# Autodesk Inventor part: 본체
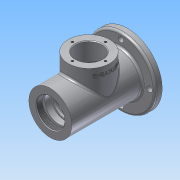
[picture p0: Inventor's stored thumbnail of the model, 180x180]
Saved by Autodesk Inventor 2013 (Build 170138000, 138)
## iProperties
Created: 2016-08
Part Number: 본체
Material: 알루미늄 6061
Document SubType Name: Modeling
Designer: Administrator
Density: 2.71 g/cm^3
Mass: 730.594 g
Surface Area: 615.602 cm^2
Volume: 269.592 cm^3
Author: Administrator
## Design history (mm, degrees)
sketch "스케치1"
  geometry: L1 (-57.5, 0)-(57.5, 0); L2 (-57.5, 0)-(-57.5, 31); L3 (-57.5, 31)-(44.5, 31); L4 (44.5, 31)-(44.5, 50); L5 (44.5, 50)-(54.5, 50); L6 (54.5, 50)-(54.5, 31); L7 (54.5, 31)-(57.5, 31); L8 (57.5, 31)-(57.5, 0); 2 further points
  constraints: 16 end point, 6 perpendicular, 1 coincident, 1 collinear, 1 horizontal, 1 midpoint, 1 parallel
  dimensions: "d0" = 100 diameter of L5 L1; "d2" = 115 distance of L1.start L1.end; "d4" = 3 horizontal distance of L7.end L5.end; "d6" = 13 distance between parallel lines of L8 L4; "d7" = 62 diameter of L3 L1
revolve "회전1" sketch "스케치1" stored, may be unused: angle "d8" = 90 deg
node "작업 평면1"
sketch "스케치2"
  geometry: L1 (57.5, 31)-(57.5, -31) reference; C1 r 30 at (1.5, 0); 1 further point
  constraints: 1 centre point, 1 horizontal alignment
  dimensions: "d10" = 60 diameter of C1; "d12" = 56 distance from line of L1 C1.centre
extrude "돌출1" join sketch "스케치2" stored distance "d13" = 10; taper "d14" = 0 deg
sketch "스케치3"
  geometry: L1 (57.5, 0)-(-48.5, 0); L2 (57.5, -31)-(57.5, 31) reference; L3 (57.5, 0)-(57.5, 21); L4 (57.5, 21)-(43.5, 16); L5 (43.5, 16)-(43.5, 12.5); L6 (43.5, 12.5)-(36.2, 12.5); L7 (36.2, 12.5)-(36.2, 10); L8 (36.2, 10)-(33.5, 10); L9 (33.5, 10)-(33.5, 16.5); L10 (33.5, 16.5)-(28.5, 16.5); L11 (28.5, 16.5)-(28.5, 17.5); L12 (28.5, 17.5)-(17.5, 17.5); L13 (17.5, 17.5)-(17.5, 26); L14 (17.5, 26)-(-20.5, 26); L15 (-20.5, 26)-(-20.5, 17.5); L16 (-20.5, 17.5)-(-31.5, 17.5); L17 (-31.5, 17.5)-(-31.5, 18.5); L18 (-31.5, 18.5)-(-33.25, 18.5); L19 (-33.25, 18.5)-(-33.25, 17.5); L20 (-33.25, 17.5)-(-36.5, 17.5); L21 (-36.5, 17.5)-(-36.5, 20); L22 (-36.5, 20)-(-45.5, 20); L23 (-45.5, 20)-(-45.5, 24); L24 (-45.5, 24)-(-48.5, 24); L25 (-48.5, 24)-(-48.5, 0); L26 (-57.5, -31)-(-57.5, 31) reference; L27 (-31.5, 49)-(28.5, 49) reference; 3 further points
  constraints: 48 end point, 15 perpendicular, 7 parallel, 3 midpoint, 2 collinear, 2 point on line, 1 horizontal, 1 vertical alignment
  dimensions: "d15" = 42 diameter of L3.end L1; "d17" = 32 diameter of L4.end L1; "d18" = 25 diameter of L6 L1; "d19" = 20 diameter of L8 L1; "d20" = 33 diameter of L10 L1; "d21" = 35 diameter of L12 L1; "d22" = 52 diameter of L14 L1; "d23" = 37 diameter of L18 L1; "d24" = 1.75 distance of L17.end L18.end; "d25" = 3 distance of L23.end L24.end; "d26" = 12 distance between parallel lines of L23 L26; "d27" = 21 distance from line of L26 L21.end; "d28" = 26 distance from line of L26 L17.end; "d29" = 40 diameter of L22 L1; "d30" = 48 diameter of L24 L1; "d31" = 14 distance between parallel lines of L3 L5; "d32" = 7.3 distance of L5.end L6.end; "d33" = 5 distance from line of L11.end L9; "d34" = 38 distance of L13.end L14.end; "d36" = 2.7 distance of L7.end L8.end
revolve "회전2" sketch "스케치3" stored, may be unused: angle "d37" = 90 deg
fillet "모깎기3" dims "d87" = 3
hole "구멍1" diameter "d40" = 38; stored, may be unused: countersink angle "d44" = 90 deg, drill point angle "d46" = 0 deg; dims "d38" = 10, "d39" = 10, "d41" = 6, "d42" = 4, "d43" = 2, "d45" = 50
hole "구멍2" diameter "d49" = 40.376; stored, may be unused: countersink angle "d53" = 90 deg, drill point angle "d55" = 0 deg; dims "d47" = 10, "d48" = 10, "d50" = 9, "d51" = 4, "d52" = 2, "d54" = 9
sketch "스케치4"
  geometry: C1 r 19 at (0, 0) reference; 2 further points
  constraints: 1 vertical alignment
  dimensions: "d56" = 24 distance of C1.centre point (0, 24)
hole "구멍3" sketch "스케치4" at (0, 24) diameter "d57" = 3.242; stored, may be unused: countersink angle "d61" = 90 deg, drill point angle "d63" = 118 deg; dims "d58" = 8, "d59" = 4, "d60" = 2, "d62" = 10
sketch "스케치5"
  geometry: 2 further points
  constraints: 1 horizontal alignment
  dimensions: "d67" = 41.5 distance of point (0, 0) point (-41.5, 0)
hole "구멍4" sketch "스케치5" at (-41.5, 0) diameter "d68" = 8; stored, may be unused: countersink angle "d72" = 90 deg, drill point angle "d74" = 0 deg; dims "d69" = 8, "d70" = 4, "d71" = 2, "d73" = 10
fillet "모깎기1" dims "d78" = 3
fillet "모깎기2" dims "d79" = 3
chamfer "모따기1" distance "d80" = 1; stored, may be unused: second distance "d81" = 2, angle "d82" = 45 deg
chamfer "모따기2" distance "d88" = 1; stored, may be unused: second distance "d89" = 2, angle "d90" = 45 deg
fillet "모깎기4" dims "d91" = 3
fillet "모깎기5" dims "d92" = 0.3
sketch "스케치6"
  geometry: L1 (42.8, 12.5)-(43.5, 12.904); L2 (43.5, 12.5)-(36.5, 12.5) reference; L3 (43.5, 13.886)-(43.5, -13.886) reference; L4 (43.5, 0)-(41.594, 0); L5 (42.8, 12.5)-(43.5, 12.5); L6 (43.5, 12.904)-(43.5, 12.5); 1 further point
  constraints: 8 end point, 2 perpendicular, 2 point on line, 1 midpoint, 1 parallel
  dimensions: "d93" = 30 deg angle of L2 L1; "d94" = 0.7 distance from line of L3 L1.start
revolve "회전3" sketch "스케치6" stored, may be unused: angle "d95" = 90 deg
fillet "모깎기6" dims "d96" = 3
node "작업 평면2"
sketch "스케치7" dims "d15" = 42, "d17" = 32, "d18" = 25, "d19" = 20, "d20" = 33, "d21" = 35, "d22" = 52, "d23" = 37, "d24" = 1.75, "d25" = 3, "d26" = 12, "d27" = 21, "d28" = 26, "d29" = 40, "d30" = 48, "d31" = 14, "d32" = 7.3, "d33" = 5, "d34" = 38, "d36" = 2.7
  geometry: L1 (-56, -80)-(-56, -18) reference; L2 (-30, 0)-(30, 0) reference; 2 further points
  constraints: 1 other
  dimensions: "d101" = 56 distance from line of L1 point (0, -10); "d102" = 10 distance from line of L2 point (0, -10)
feature "엠보싱1" sketch "스케치7" dims "d103" = 0.5, "d104" = 0
fillet "모깎기7" dims "d109" = 0.3
node "솔리드1"
pattern_circular "원형 패턴1" dims angle "d65" = 360 deg
pattern_circular "원형 패턴2" dims angle "d76" = 360 deg
other parameters: "d9" = 49
